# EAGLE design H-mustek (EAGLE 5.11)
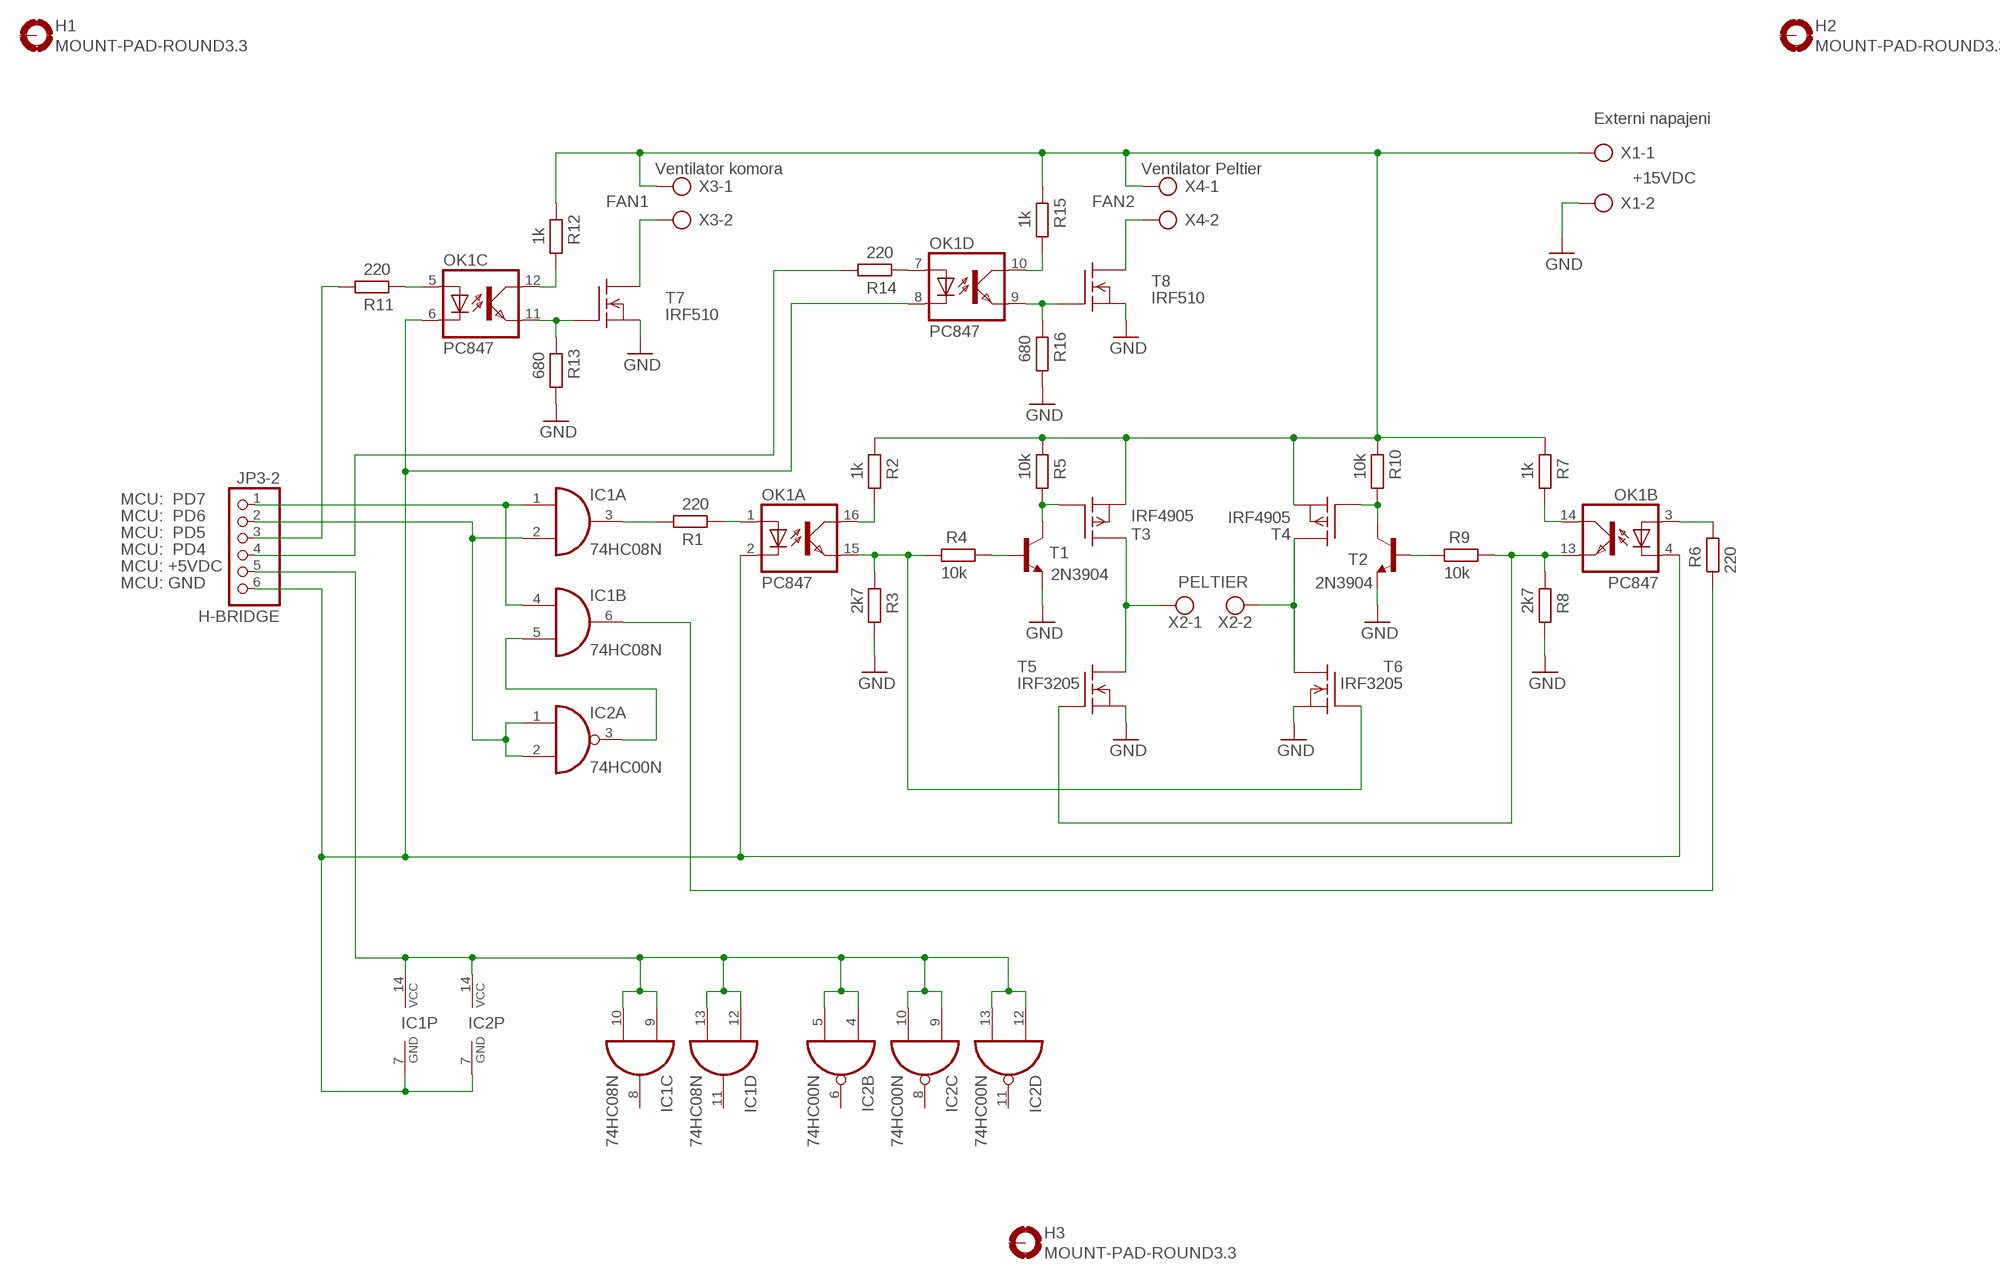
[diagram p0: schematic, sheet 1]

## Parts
H1  MOUNT-PAD-ROUND3.3  [3,3-PAD]
H2  MOUNT-PAD-ROUND3.3  [3,3-PAD]
H3  MOUNT-PAD-ROUND3.3  [3,3-PAD]
IC1  74HC08N  74AC08N  [DIL14]
IC2  74HC00N  74AC00N  [DIL14]
JP3-2  H-BRIDGE  PINHD-1X6  [1X06]
OK1  PC847  [DIL16]
R1  220  R-EU_0207/7  [0207/7]
R2  1k  R-EU_0207/7  [0207/7]
R3  2k7  R-EU_0207/7  [0207/7]
R4  10k  R-EU_0207/7  [0207/7]
R5  10k  R-EU_0207/7  [0207/7]
R6  220  R-EU_0207/7  [0207/7]
R7  1k  R-EU_0207/7  [0207/7]
R8  2k7  R-EU_0207/7  [0207/7]
R9  10k  R-EU_0207/7  [0207/7]
R10  10k  R-EU_0207/7  [0207/7]
R11  220  R-EU_0207/7  [0207/7]
R12  1k  R-EU_0207/7  [0207/7]
R13  680  R-EU_0207/7  [0207/7]
R14  220  R-EU_0207/7  [0207/7]
R15  1k  R-EU_0207/7  [0207/7]
R16  680  R-EU_0207/7  [0207/7]
T1  2N3904  [TO92]
T2  2N3904  [TO92]
T3  IRF4905  IRF9530V  [TO220V]
T4  IRF4905  IRF9530V  [TO220V]
T5  IRF3205  IRF540V  [TO220V]
T6  IRF3205  IRF540V  [TO220V]
T7  IRF510  IRF540V  [TO220V]
T8  IRF510  IRF540V  [TO220V]
X1  +15VDC  AK500/2  [AK500/2]
X2  PELTIER  AK500/2  [AK500/2]
X3  FAN1  AK500/2  [AK500/2]
X4  FAN2  AK500/2  [AK500/2]

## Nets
12VDC: R2.2 R5.2 R7.2 R10.2 R12.2 R15.2 T3.3(S) T4.3(S) X1.1 X3.1 X4.1
GND: R3.1 R8.1 R13.1 R16.1 T1.3(E) T2.3(E) T5.3(S) T6.3(S) T7.3(S) T8.3(S) X1.2
N$1: R5.1 T1.1(C) T3.1(G)
N$2: OK1.13(B:EMIT) R8.2 R9.1 T5.1(G)
N$3: OK1.3(B:A) R6.1
N$4: R4.1 T1.2(B)
N$5: IC1.3(A:O) R1.1
N$6: OK1.16(A:COL) R2.1
N$7: OK1.15(A:EMIT) R3.2 R4.2 T6.1(G)
N$8: R10.1 T2.1(C) T4.1(G)
N$9: OK1.1(A:A) R1.2
N$10: R9.2 T2.2(B)
N$11: IC1.1(A:I0) IC1.4(B:I0) JP3-2.1
N$12: OK1.14(B:COL) R7.1
N$13: IC1.2(A:I1) IC2.1(A:I0) IC2.2(A:I1) JP3-2.2
N$14: IC1.5(B:I1) IC2.3(A:O)
N$15: OK1.11(C:EMIT) R13.2 T7.1(G)
N$16: OK1.7(D:A) R14.2
N$17: IC1.6(B:O) R6.2
N$18: IC1.9(C:I0) IC1.10(C:I1) IC1.12(D:I0) IC1.13(D:I1) IC1.14(P:VCC) IC2.4(B:I0) IC2.5(B:I1) IC2.9(C:I0) IC2.10(C:I1) IC2.12(D:I0) IC2.13(D:I1) IC2.14(P:VCC) JP3-2.5
N$19: OK1.12(C:COL) R12.1
N$20: IC1.7(P:GND) IC2.7(P:GND) JP3-2.6 OK1.2(A:C) OK1.4(B:C) OK1.6(C:C) OK1.8(D:C)
N$21: OK1.5(C:A) R11.2
N$22: JP3-2.3 R11.1
N$23: T7.2(D) X3.2
N$25: JP3-2.4 R14.1
N$28: OK1.9(D:EMIT) R16.2 T8.1(G)
N$29: T8.2(D) X4.2
N$30: OK1.10(D:COL) R15.1
PELTIER_1: T4.2(D) T6.2(D) X2.2
PELTIER_2: T3.2(D) T5.2(D) X2.1
Unconnected: H1.B3,3(MOUNT) H2.B3,3(MOUNT) H3.B3,3(MOUNT) IC1.8(C:O) IC1.11(D:O) IC2.6(B:O) IC2.8(C:O) IC2.11(D:O)

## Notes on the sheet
- Externi napajeni
- Ventilator komora | Ventilator Peltier
- MCU:  PD7
- MCU:  PD6
- MCU:  PD5
- MCU:  PD4
- MCU: +5VDC
- MCU: GND

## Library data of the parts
H1-H3 = holes:MOUNT-PAD-ROUND: MOUNTING PAD, round
IC1 = 74xx-eu:74*08: Quad 2-input AND gate
IC2 = 74xx-eu:74*00: Quad 2-input NAND gate
JP3-2 = pinhead:PINHD-1X6: PIN HEADER
OK1 = optocoupler:PC847: SHARP OPTO COUPLER; OC_FARNELL: 9707735; OC_NEWARK: unknown
R1-R16 = rcl:R-EU_: RESISTOR, European symbol
T1 T2 = transistor-npn:2N3904: NPN Transistor
T3 T4 = transistor-fet:IRF9530: P-Channel Enhancement MOSFET (HEXFET); -100V; -12A; 0,3Ohm
T5-T8 = transistor-fet:IRF540: N-Channel Enhancement MOSFET (HEXFET); 100V; 28A; 0,077Ohm
X1-X4 = con-ptr500:AK500/2: CONNECTOR; OC_FARNELL: unknown; OC_NEWARK: unknown

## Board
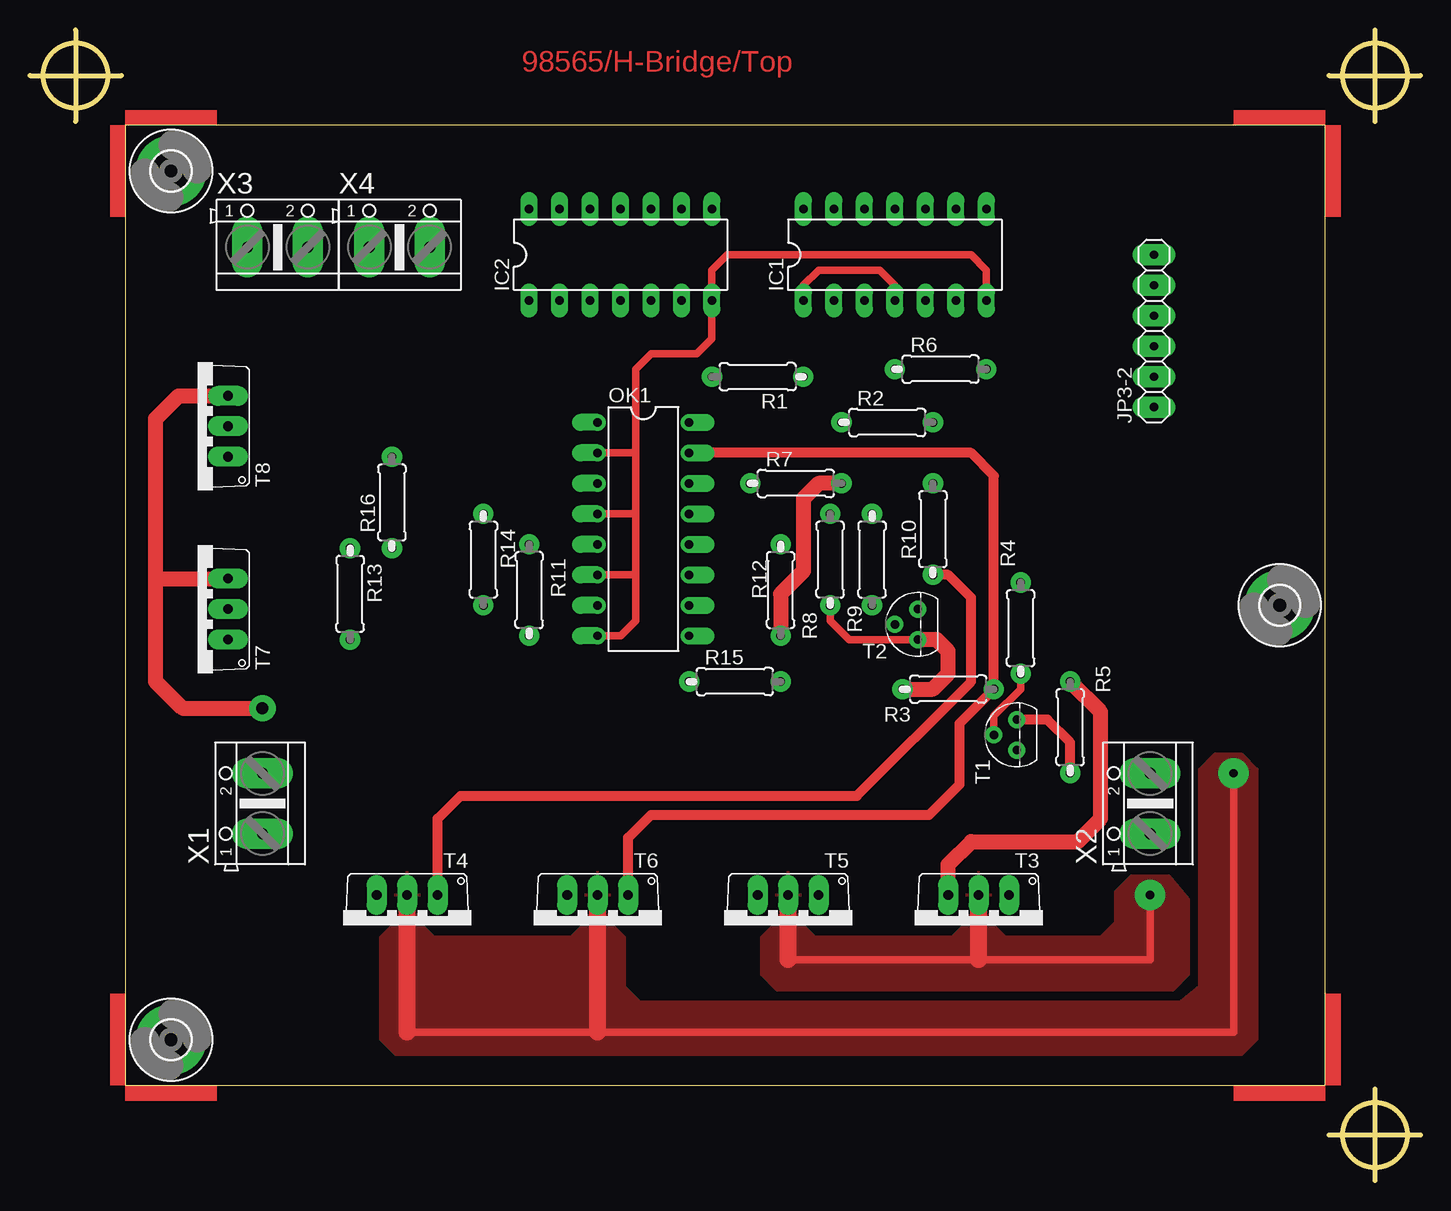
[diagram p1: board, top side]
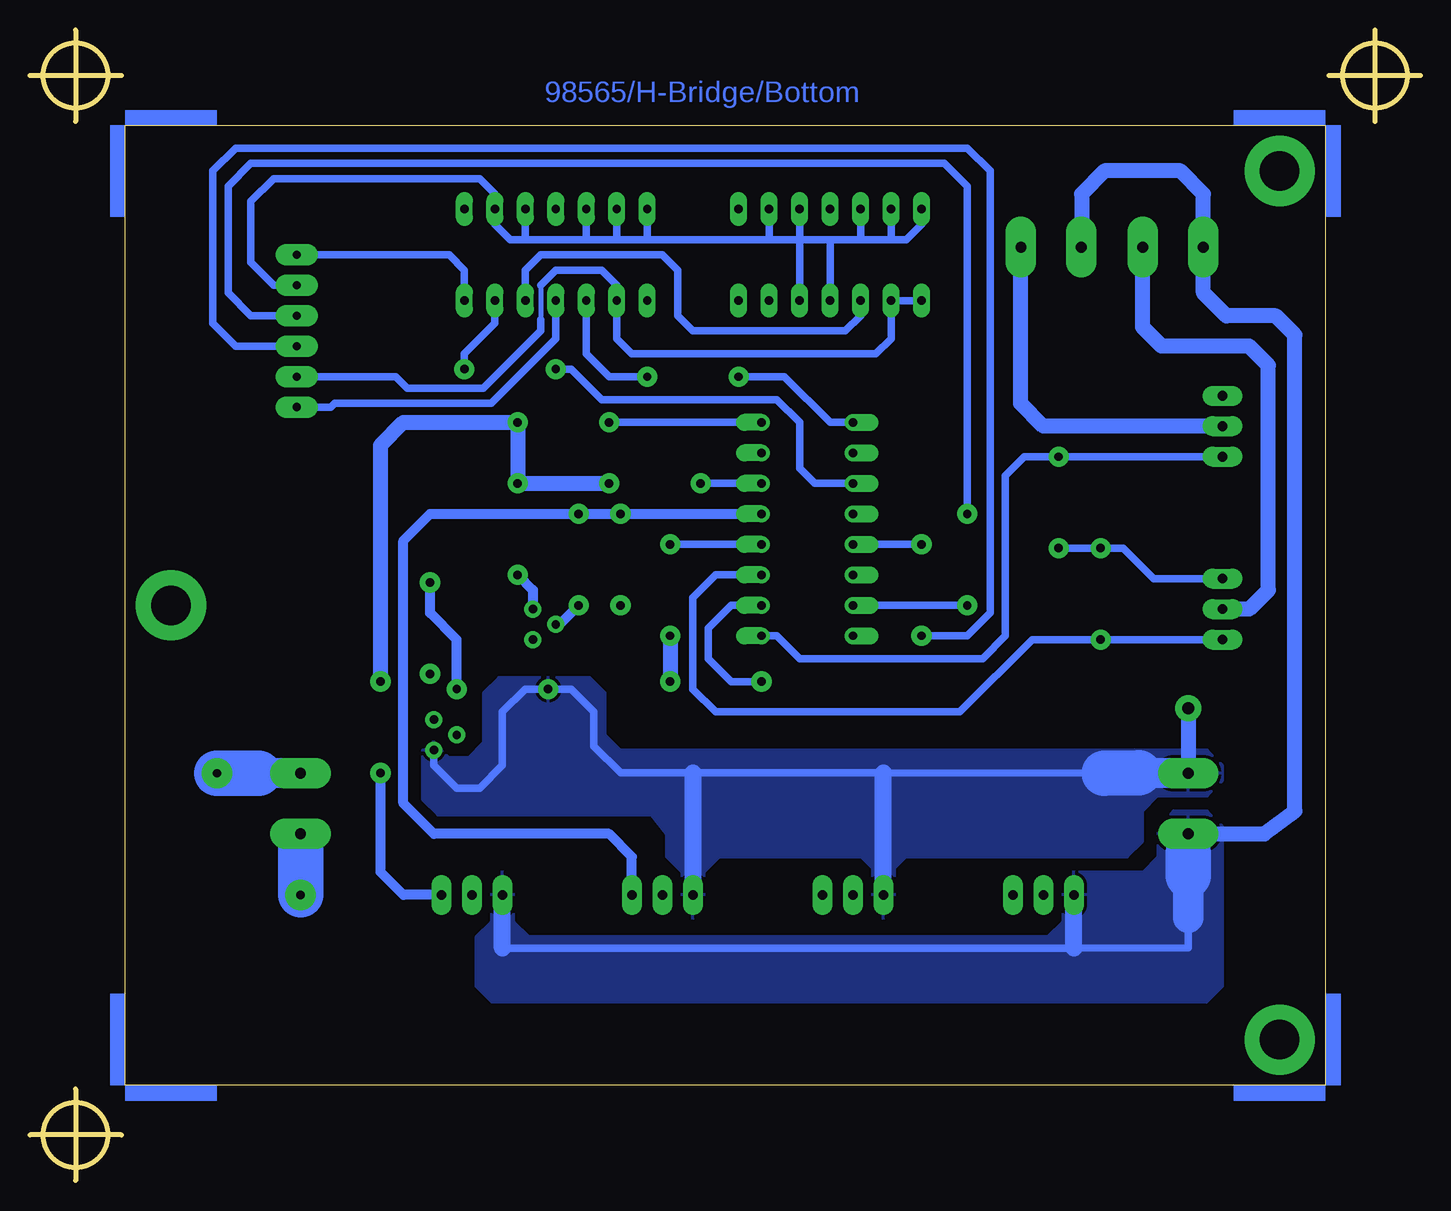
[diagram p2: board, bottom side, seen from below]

Size 115.89 x 95.89 mm. Coordinates in mm from the lower left corner, seen from the top.
Outline: 108.27,3.81 115.89,3.81
Outline: 112.08,7.62 112.08,0
Outline: 0,92.08 7.62,92.08
Outline: 3.81,95.89 3.81,88.27
Outline: 108.27,92.08 115.89,92.08
Outline: 112.08,95.89 112.08,88.27
Outline: 7.94,7.94 107.94,7.94 107.94,87.94 7.94,87.94 7.94,7.94
Outline: circle at 112.08,3.81 radius 2.69
Outline: circle at 112.08,92.08 radius 2.69
Outline: circle at 3.81,92.08 radius 2.69
Copper layers (1*16): Top 0.035mm / dielectric 1.5mm / Bottom 0.035mm
Design rules "default": minimum track width 10mil, minimum drill 24mil, track to track 8mil, track to pad 8mil, pad to pad 8mil, via to via 8mil, smd to smd 8mil, copper to edge 40mil, drill to drill 8mil, minimum pad ring 10mil, minimum via ring 8mil, stop-mask expansion 4mil, vias tented up to drill 0mil, thermal gap 10mil

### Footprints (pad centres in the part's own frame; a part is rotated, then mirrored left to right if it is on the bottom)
3,3-PAD = drill 3.3 pad 5.842 round: B3,3 0,0
DIL14 = drill 0.7 pad 1.422 long: 1 -7.62,-3.81; 2 -5.08,-3.81; 3 -2.54,-3.81; 4 0,-3.81; 5 2.54,-3.81; 6 5.08,-3.81; 7 7.62,-3.81; 8 7.62,3.81; 9 5.08,3.81; 10 2.54,3.81; 11 0,3.81; 12 -2.54,3.81; 13 -5.08,3.81; 14 -7.62,3.81
1X06 = drill 0.7 pad 1.778 long: 1 -6.35,0; 2 -3.81,0; 3 -1.27,0; 4 1.27,0; 5 3.81,0; 6 6.35,0
DIL16 = drill 0.7 pad 1.422 offset: 1 -8.89,-3.81; 2 -6.35,-3.81; 3 -3.81,-3.81; 4 -1.27,-3.81; 5 1.27,-3.81; 6 3.81,-3.81; 7 6.35,-3.81; 8 8.89,-3.81; 9 8.89,3.81; 10 6.35,3.81; 11 3.81,3.81; 12 1.27,3.81; 13 -1.27,3.81; 14 -3.81,3.81; 15 -6.35,3.81; 16 -8.89,3.81
0207/7 = drill 0.7 pad 1.676 round: 1 -3.81,0; 2 3.81,0
TO92 = drill 0.7 pad 1.422 round: 1 1.27,0; 2 0,1.905; 3 -1.27,0
TO220V = drill 0.8 pad 1.676 long: 1 -2.54,-2.54; 2 0,-2.54; 3 2.54,-2.54
AK500/2 = drill 0.9 pad 2.54 long: 1 -2.515,0; 2 2.515,0

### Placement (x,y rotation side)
H1  11.75,11.75 0 top
H2  11.75,84.14 0 top
H3  104.14,47.94 0 top
IC1  72.07,77.15 0 top
IC2  49.21,77.15 0 top
JP3-2  93.66,70.8 90 top
OK1  51.12,54.29 270 top
R1  60.64,66.99 180 top
R2  71.44,63.18 0 top
R3  76.52,40.96 0 top
R4  82.55,46.04 90 top
R5  86.68,37.78 90 top
R6  75.88,67.63 0 top
R7  63.82,58.1 0 top
R8  66.67,51.75 90 top
R9  70.17,51.75 270 top
R10  75.25,54.29 90 top
R11  41.59,49.21 90 top
R12  62.55,49.21 270 top
R13  26.67,48.9 270 top
R14  37.78,51.75 270 top
R15  58.74,41.59 0 top
R16  30.16,56.52 90 top
T1  82.23,37.15 90 top
T2  73.98,46.35 90 top
T3  79.06,21.27 180 top
T4  31.43,21.27 180 top
T5  63.18,21.27 180 top
T6  47.31,21.27 180 top
T7  13.97,47.62 90 top
T8  13.97,62.87 90 top
U$1  [ANGLE-ARROW-NW1-16]  7.94,87.95 0 top
U$2  [ANGLE-ARROW-NW1-16]  107.95,87.95 270 top
U$3  [ANGLE-ARROW-NW1-16]  107.95,7.94 180 top
U$4  [ANGLE-ARROW-NW1-16]  7.94,7.94 90 top
X1  19.37,31.43 90 top
X2  93.34,31.43 90 top
X3  20.64,77.79 0 top
X4  30.8,77.79 0 top

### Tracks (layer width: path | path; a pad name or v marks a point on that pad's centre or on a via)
12VDC
  Top 1.27: T3.3 76.52,26.35 78.42,28.26 87.31,28.26 89.22,30.16 89.22,39.05 R5.2 | R7.2 65.72,58.1 64.45,56.83 64.45,50.8 62.55,48.9 R12.2
  Bottom 0.61: 19.37,21.91 19.37,19.39 28.89,19.37 76.52,19.37
  Bottom 1.27: R5.2 86.68,61.28 84.77,63.18 R2.2 R10.2 R7.2 | R12.2 R15.2 | X1.1 13.02,28.89 10.48,30.8 10.48,70.48 12.07,72.07 16.19,72.07 18.1,73.98 18.1,77.76 X3.1 18.1,82.23 20,84.14 26.35,84.14 28.26,82.23 X4.1
  Bottom 1.422: 28.89,19.37 T4.3 | 76.52,19.37 T3.3
  Bottom 2.54: 19.37,21.91 19.37,25.4 | 19.37,27.3 X1.1
  Bottom 3.81: 19.37,25.4 19.37,27.3
  pour Bottom (isolate 0.61): 16.51,16.19 16.51,29.53 17.78,30.8 20.64,30.8 21.91,29.53 21.91,26.99 23.18,25.72 29.21,25.72 29.84,25.08 29.84,21.59 31.11,20.32 74.3,20.32 75.56,21.59 75.56,25.08 76.2,25.72 76.83,25.72 77.47,25.08 77.47,21.59 78.74,20.32 78.74,16.19 77.47,14.92 17.78,14.92
GND  (via drill 1 pad 2.18)
  Top 0.61: R8.1 66.67,46.67 68.26,45.09 T2.3
  Top 1.27: T2.3 75.56,45.09 76.52,44.13 76.52,42.23 75.25,40.96 R3.1 | T8.3 12.38,65.41 10.48,63.5 10.48,50.16 | 10.48,50.16 T7.3 | 10.48,50.16 10.48,41.59 12.7,39.37 v19.37,39.37
  Bottom 0.61: 23.49,33.97 44.77,33.95 T6.3 | 44.77,33.97 60.64,33.97 66.67,33.97 68.9,36.2 68.9,39.05 70.8,40.96 R3.1 74.61,40.96 76.52,39.05 76.52,34.61 78.42,32.7 80.33,32.7 82.23,34.61 T1.3 | R16.1 R13.1 24.77,52.7 22.22,50.16 T7.3
  Bottom 1.27: v19.37,39.37 X1.2
  Bottom 1.422: T6.3 44.77,33.97 | 60.64,33.97 T5.3
  Bottom 2.54: X1.2 23.49,33.97
  Bottom 3.81: 23.49,33.97 26.35,33.95
  pour Bottom: 16.51,33.34 16.51,34.61 17.78,35.88 66.67,35.88 67.94,37.15 67.94,40.64 69.22,41.91 76.83,41.91 78.11,40.64 78.11,36.51 79.38,35.24 80.96,35.24 81.6,35.88 81.6,36.2 81.92,36.51 82.55,36.51 83.19,35.88 83.19,31.75 81.92,30.48 64.13,30.48 62.87,28.89 62.87,26.99 61.59,25.72 61.59,22.54 60.96,21.91 60.33,21.91 59.69,22.54 59.69,25.72 58.42,26.99 46.67,26.99 45.72,26.04 45.72,22.54 45.09,21.91 44.45,21.91 43.81,22.54 43.81,26.04 42.86,26.99 24.45,26.99 23.18,28.26 23.18,30.8 21.91,32.07 17.78,32.07
N$1
  Top 0.813: T1.1 84.77,38.42 86.68,36.51 R5.1
  Bottom 0.813: R5.1 86.68,25.72 84.77,23.81 T3.1
N$2
  Bottom 0.813: OK1.13 R8.2 R9.1 82.55,55.56 84.77,53.34 84.77,31.43 82.23,28.89 67.63,28.89 65.72,26.99 T5.1
N$3
  Bottom 0.61: OK1.3 50.48,58.1 51.75,59.37 51.75,63.18 53.66,65.09 68.26,65.09 70.8,67.63 R6.1
N$4
  Top 0.61: R4.1 82.55,40.96 80.33,38.73 T1.2
N$5
  Bottom 0.61: R1.1 67.63,66.99 69.53,68.9 IC1.3
N$6
  Bottom 0.61: OK1.16 R2.1
N$7
  Top 0.813: OK1.15 78.42,60.64 80.33,58.74 R3.2 77.47,38.1 77.47,33.02 74.93,30.48 51.75,30.48 49.85,28.57 T6.1
  Bottom 0.813: R4.2 82.55,47.31 80.33,45.09 R3.2
N$8
  Top 0.813: T4.1 33.97,30.16 35.88,32.07 68.9,32.07 78.42,41.59 78.42,48.58 76.52,50.48 R10.1
  Bottom 0.813: R10.1 73.98,49.21 T2.1
N$9
  Bottom 0.61: OK1.1 49.21,63.18 53.02,66.99 R1.2
N$10
  Bottom 0.813: T2.2 71.76,46.35 R9.2
N$11
  Top 0.61: IC1.1 64.45,74.61 65.72,75.88 70.8,75.88 72.07,74.61 IC1.4
  Bottom 0.61: JP3-2.1 90.81,64.45 90.49,64.77 77.47,64.77 72.07,70.17 IC1.4
N$12
  Bottom 0.61: OK1.14 R7.1
N$13
  Bottom 0.406: 73.34,74.61 73.34,71.76
  Bottom 0.61: IC2.1 IC2.2 44.13,70.17 45.4,68.9 65.72,68.9 66.99,70.17 IC1.2 66.99,74.61 68.26,75.88 72.07,75.88 73.34,74.61 | JP3-2.2 85.41,66.99 84.45,66.04 78.11,66.04 73.34,70.8 73.34,71.76
N$14
  Bottom 0.61: IC2.3 46.67,72.07 47.94,70.8 60.64,70.8 61.91,72.07 61.91,75.88 63.18,77.15 73.34,77.15 74.61,75.88 IC1.5
N$15
  Bottom 0.61: T7.1 R13.2 32.39,45.09 38.42,39.05 58.74,39.05 60.64,40.96 60.64,48.58 58.74,50.48 OK1.11
N$16
  Bottom 0.61: R14.2 OK1.7
N$17
  Bottom 0.61: R6.2 79.69,68.9 77.15,71.44 IC1.6
N$18
  Bottom 0.61: JP3-2.5 95.57,74.61 97.47,76.52 97.47,81.6 95.57,83.5 78.42,83.5 77.15,82.23 IC1.9 77.15,79.69 75.88,78.42 74.61,78.42 | IC2.14 41.59,79.69 42.86,78.42 44.13,78.42 | 44.13,78.42 IC2.13 | 44.13,78.42 46.67,78.42 | 46.67,78.42 IC2.12 | 46.67,78.42 49.21,78.42 | 51.75,78.42 54.29,78.42 | 54.29,78.42 IC2.9 | 54.29,78.42 64.45,78.42 | 64.45,78.42 IC1.14 | 64.45,78.42 66.99,78.42 | 66.99,78.42 IC1.13 | 66.99,78.42 69.53,78.42 | 69.53,78.42 IC1.12 | 69.53,78.42 74.61,78.42 | 74.61,78.42 IC1.10 | 51.75,78.42 IC2.10 | 51.75,78.42 IC2.5 | 49.21,78.42 51.75,78.42 | 49.21,78.42 IC2.4
N$19
  Bottom 0.61: OK1.12 R12.1
N$20
  Top 0.61: 50.48,60.64 OK1.2 | 50.48,55.56 50.48,60.64 | 50.48,55.56 OK1.4 | 50.48,50.48 50.48,55.56 | 50.48,50.48 OK1.6 | OK1.8 49.21,45.4 50.48,46.67 50.48,50.48 | 50.48,60.64 50.48,67.63 51.75,68.9 55.56,68.9 56.83,70.17 IC2.7 56.83,75.88 58.1,77.15 78.42,77.15 79.69,75.88 IC1.7
  Bottom 0.61: JP3-2.6 80.96,77.15 79.69,75.88 IC1.7
N$21
  Bottom 0.61: R11.2 OK1.5
N$22
  Bottom 0.61: JP3-2.3 98.74,69.53 100.65,71.44 100.65,84.14 98.74,86.04 37.78,86.04 35.88,84.14 35.88,47.31 37.78,45.4 R11.1
N$23
  Bottom 1.27: T7.2 14.29,47.63 12.7,49.21 12.7,67.95 14.29,69.53 21.59,69.53 23.18,71.12 23.18,77.76 X3.2
N$25
  Bottom 0.61: R14.1 37.78,82.87 39.69,84.77 97.47,84.77 99.38,82.87 99.38,73.98 97.47,72.07 JP3-2.4
N$28
  Bottom 0.61: T8.1 R16.2 33.02,60.33 34.61,58.74 34.61,45.4 36.51,43.5 51.75,43.5 53.66,45.4 OK1.9
N$29
  Bottom 1.27: T8.2 31.43,62.87 33.34,64.77 33.34,77.76 X4.2
N$30
  Bottom 0.61: R15.1 57.47,41.59 59.37,43.5 59.37,46.04 57.47,47.94 OK1.10
PELTIER_1  (via drill 0.7 pad 2.54)
  Top 0.61: v100.3,33.95 100.33,33.97 100.33,12.38 47.31,12.38 31.43,12.38
  Top 1.422: 47.31,12.38 T6.2 | 31.43,12.38 T4.2
  Bottom 2.54: 96.84,33.95 96.84,33.97 X2.2
  Bottom 3.81: v100.3,33.95 96.84,33.95
  pour Top (isolate 0.61): 29.21,11.75 29.21,20.32 30.48,21.59 30.48,25.08 31.11,25.72 31.75,25.72 32.39,25.08 32.39,21.59 33.66,20.32 45.09,20.32 46.35,21.59 46.35,25.08 46.99,25.72 47.62,25.72 48.26,25.08 48.26,21.59 49.53,20.32 49.53,16.19 50.8,14.92 95.89,14.92 97.47,16.19 97.47,34.29 98.74,35.56 100.97,35.56 102.23,34.29 102.23,11.75 100.97,10.48 30.48,10.48
PELTIER_2  (via drill 0.7 pad 2.54)
  Top 0.61: v93.34,23.81 93.34,18.41 79.06,18.41 63.18,18.41
  Top 1.422: 79.06,18.41 T3.2 | 63.18,18.41 T5.2
  Bottom 2.54: 93.34,27.62 X2.1
  Bottom 3.81: v93.34,23.81 93.34,27.62
  pour Top (isolate 0.61): 60.96,17.14 60.96,20.32 62.23,21.59 62.23,25.08 62.87,25.72 63.5,25.72 64.13,25.08 64.13,21.59 65.41,20.32 76.83,20.32 78.11,21.59 78.11,25.08 78.74,25.72 79.38,25.72 80.01,25.08 80.01,21.59 81.28,20.32 89.22,20.32 90.49,21.59 90.49,24.13 91.76,25.4 94.93,25.4 96.52,23.49 96.52,17.14 95.25,15.88 62.23,15.88

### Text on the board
Top: 98565/H-Bridge/Top
Bottom: 98565/H-Bridge/Bottom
